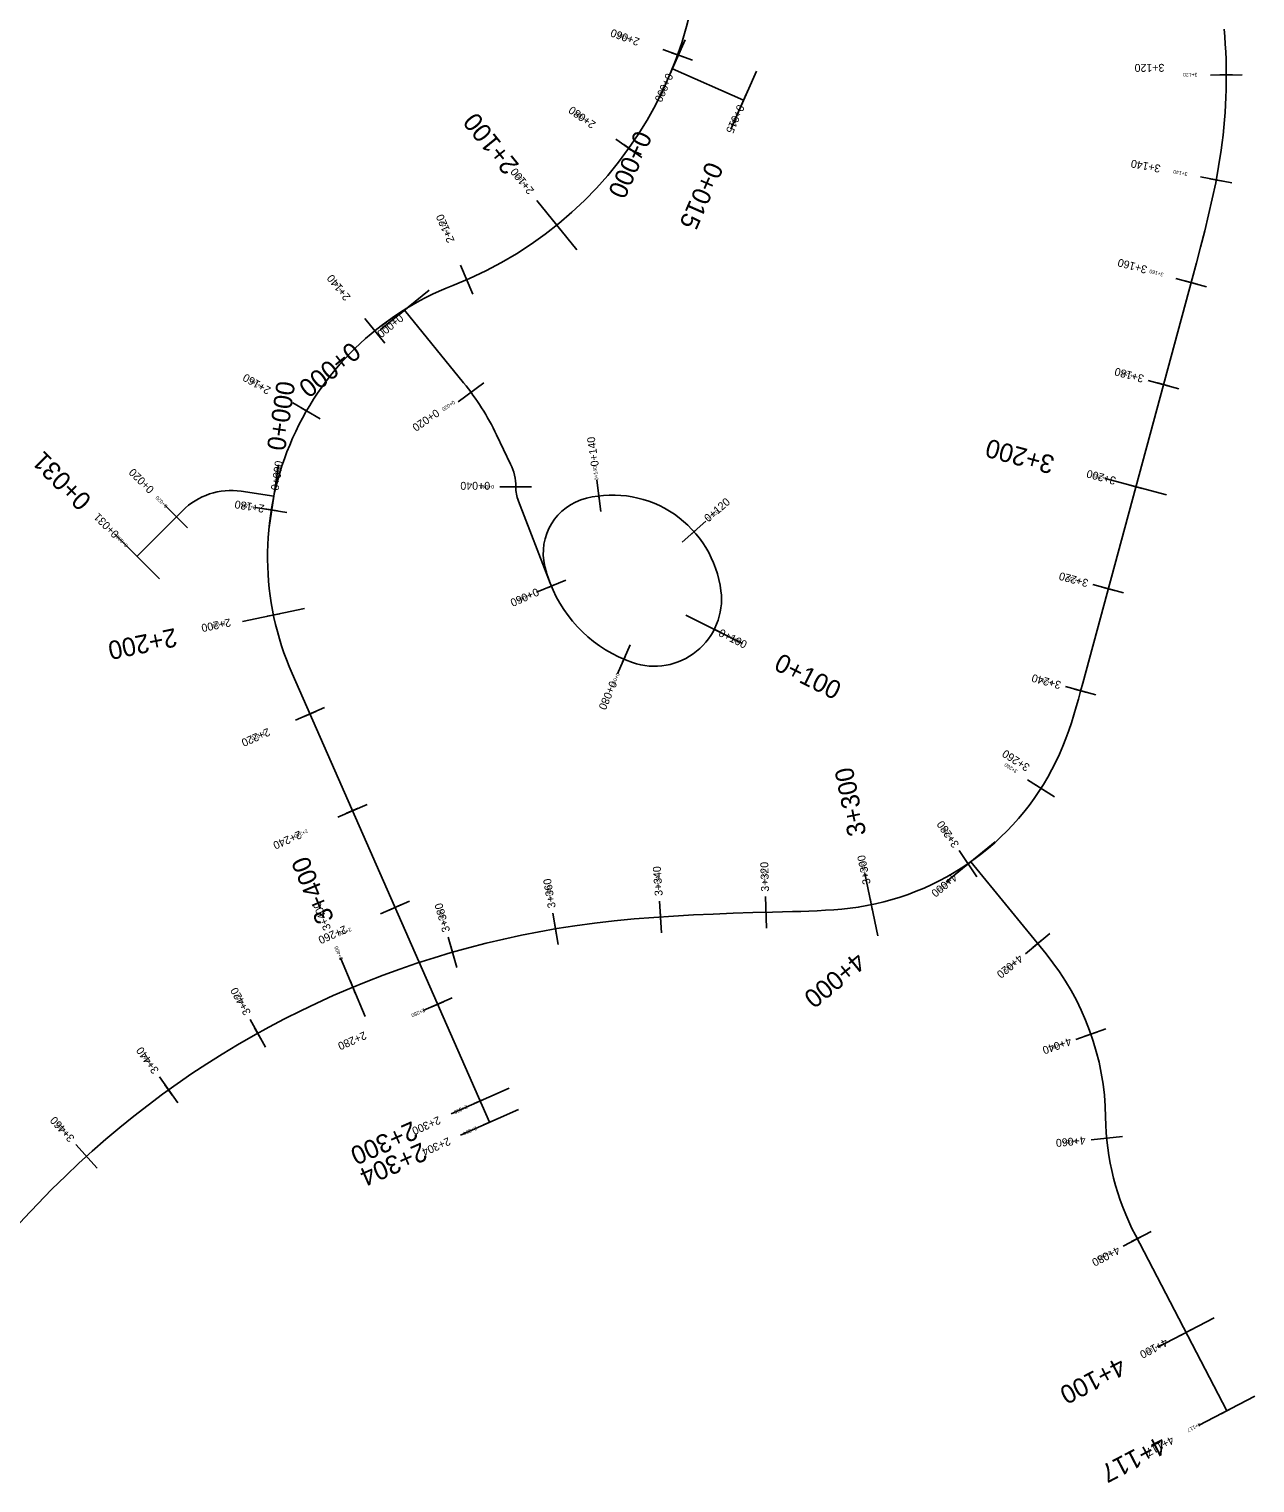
# Model space of a CAD drawing. Extents: x 0 to 511895, y 0 to 6211943.
# Drawn here: x 511516.6 to 511748.6, y 6211454.1 to 6211729.2 of the extents above; entities that cross this region are included whole.
import ezdxf

# ---------------------------------------------------------------- set-up
doc = ezdxf.new("R2010")
doc.units = 0
for name, color, linetype in [('TV_L_---_CL---_C', 7, 'Continuous'), ('TV_L_---_CL---_L', 7, 'Continuous'), ('TV_L_---_CL---_TC', 7, 'Continuous'), ('TV_L_HOR_Statn_T_00200', 7, 'Continuous'), ('TV_L_HOR_Statn_T_00500', 7, 'Continuous'), ('TV_L_HOR_Statn_T_01000', 7, 'Continuous'), ('TV_L_HOR_Statn_Tic_00200', 7, 'Continuous'), ('TV_L_HOR_Statn_Tic_00500', 7, 'Continuous'), ('TV_L_HOR_Statn_Tic_01000', 7, 'Continuous')]:
    doc.layers.add(name, color=color, linetype=linetype)

msp = doc.modelspace()

# ---------------------------------------------------------------- linework, layer by layer
at = {"layer": 'TV_L_---_CL---_C'}
for centre, radius, start, end in [((511570.29, 6211749.09), 73.36, 291.215, 13.0225), ((511643.18, 6211720.15), 100, 352.0321, 5.1862), ((511616.74, 6211629.43), 55, 111.215, 203.7372), ((511560.01, 6211630.79), 50, 25.6143, 39.0403), ((511598.72, 6211642.57), 10, 0.097, 25.6143), ((511554.86, 6211628.89), 13, 81.5953, 135.0684), ((511616.22, 6211642.6), 7.5, 180.097, 201.1169), ((511624.63, 6211630.04), 10.7, 103.7746, 193.7724), ((511627.01, 6211620.33), 20.7, 7.1648, 103.7746), ((511639.2, 6211633.62), 25.7, 193.7724, 200.2452), ((511639.2, 6211633.62), 25.7, 201.1169, 250.9171), ((511634.95, 6211621.33), 12.7, 250.9171, 7.1648), ((511666, 6211612.51), 50, 278.6766, 337.7081), ((511645.09, 6211386.34), 175, 98.2732, 133.988), ((511670.35, 6211522.56), 50, 0.8553, 39.2603), ((511770.34, 6211524.05), 50, 180.8553, 207.4882)]:
    msp.add_arc(centre, radius, start, end, dxfattribs=at)
at = {"layer": 'TV_L_---_CL---_L'}
for p, q in [((511638.35, 6211721.69), (511651.84, 6211715.76)), ((511736.7, 6211681.92), (511716.03, 6211605.46)), ((511587.69, 6211676.04), (511598.84, 6211662.28)), ((511605.09, 6211652.41), (511607.74, 6211646.89)), ((511562.94, 6211640.84), (511556.76, 6211641.75)), ((511609.22, 6211639.9), (511615.23, 6211624.36)), ((511545.66, 6211638.07), (511537.04, 6211629.43)), ((511566.39, 6211607.29), (511603.74, 6211522.36)), ((511694.81, 6211571.64), (511709.07, 6211554.2)), ((511725.99, 6211500.98), (511743.27, 6211467.75))]:
    msp.add_line(p, q, dxfattribs=at)
at = {"layer": 'TV_L_---_CL---_TC'}
for points in [[(511742.21, 6211706.29), (511741.73, 6211703.2), (511741.17, 6211700.13), (511740.53, 6211697.07), (511739.84, 6211694.02), (511739.1, 6211690.99), (511738.32, 6211687.96), (511737.52, 6211684.94), (511736.7, 6211681.92)], [(511716.03, 6211605.46), (511715.62, 6211603.95), (511715.2, 6211602.44), (511714.78, 6211600.94), (511714.33, 6211599.44), (511713.86, 6211597.95), (511713.37, 6211596.47), (511712.84, 6211595), (511712.27, 6211593.54)], [(511673.55, 6211563.08), (511672, 6211562.87), (511670.45, 6211562.7), (511668.89, 6211562.57), (511667.33, 6211562.46), (511665.77, 6211562.38), (511664.21, 6211562.32), (511662.65, 6211562.27), (511661.08, 6211562.23)], [(511661.08, 6211562.23), (511657.33, 6211562.13), (511653.58, 6211562.02), (511649.83, 6211561.9), (511646.08, 6211561.76), (511642.33, 6211561.58), (511638.58, 6211561.37), (511634.84, 6211561.12), (511631.1, 6211560.82), (511627.36, 6211560.45), (511623.63, 6211560.02), (511619.91, 6211559.52)], [(511523.56, 6211512.25), (511520.88, 6211509.62), (511518.26, 6211506.93), (511515.69, 6211504.2), (511513.16, 6211501.43), (511510.66, 6211498.62), (511508.2, 6211495.79), (511505.77, 6211492.93), (511503.36, 6211490.05), (511500.97, 6211487.16), (511498.59, 6211484.26), (511496.21, 6211481.35)]]:
    msp.add_lwpolyline(points, dxfattribs=at)
at = {"layer": 'TV_L_HOR_Statn_Tic_00200'}
for points in [[(511638.83, 6211722.79), (511637.86, 6211720.59)], [(511640.47, 6211723.91), (511638.21, 6211724.72)], [(511744.38, 6211720.52), (511741.98, 6211720.51)], [(511652.32, 6211716.86), (511651.35, 6211714.66)], [(511652.32, 6211716.86), (511651.35, 6211714.66)], [(511652.08, 6211716.31), (511651.6, 6211715.21)], [(511631.1, 6211705.94), (511629.14, 6211707.33)], [(511742.45, 6211700.41), (511740.09, 6211700.87)], [(511617.24, 6211691.16), (511615.73, 6211693.03)], [(511599.91, 6211680.66), (511598.95, 6211682.87)], [(511737.67, 6211680.91), (511735.35, 6211681.53)], [(511588.62, 6211676.79), (511586.76, 6211675.28)], [(511582.79, 6211671.16), (511581.27, 6211673.02)], [(511732.45, 6211661.6), (511730.13, 6211662.23)], [(511600.73, 6211660.83), (511599.76, 6211660.12)], [(511570.17, 6211656.36), (511568.09, 6211657.56)], [(511727.23, 6211642.29), (511724.91, 6211642.92)], [(511562.76, 6211639.65), (511563.11, 6211642.02)], [(511609.32, 6211642.58), (511608.12, 6211642.58)], [(511624.53, 6211640.28), (511624.38, 6211641.47)], [(511545.36, 6211636.07), (511543.66, 6211637.77)], [(511563.63, 6211638.03), (511561.26, 6211638.41)], [(511642.01, 6211633.71), (511642.91, 6211634.51)], [(511537.89, 6211628.59), (511536.19, 6211630.28)], [(511537.89, 6211628.59), (511536.19, 6211630.28)], [(511616, 6211624.03), (511614.89, 6211623.57)], [(511722.01, 6211622.99), (511719.69, 6211623.61)], [(511564.05, 6211618.58), (511561.7, 6211618.09)], [(511645.22, 6211616.16), (511647.37, 6211615.08)], [(511629.41, 6211610.51), (511628.94, 6211609.4)], [(511716.79, 6211603.68), (511714.47, 6211604.31)], [(511570.87, 6211600.1), (511568.67, 6211599.13)], [(511709.13, 6211584.91), (511707.1, 6211586.2)], [(511578.92, 6211581.79), (511576.72, 6211580.82)], [(511694.97, 6211570.29), (511693.61, 6211572.27)], [(511695.74, 6211572.4), (511693.88, 6211570.89)], [(511586.97, 6211563.48), (511584.77, 6211562.52)], [(511656.12, 6211560.9), (511656.05, 6211563.3)], [(511676.25, 6211562.34), (511675.76, 6211564.7)], [(511616.44, 6211557.76), (511616.04, 6211560.13)], [(511636.19, 6211560.01), (511636.02, 6211562.41)], [(511597.08, 6211553.38), (511596.41, 6211555.68)], [(511708.4, 6211556.92), (511706.54, 6211555.4)], [(511578.34, 6211546.81), (511577.42, 6211549.03)], [(511595.02, 6211545.17), (511592.82, 6211544.21)], [(511560.48, 6211538.15), (511559.31, 6211540.25)], [(511718.7, 6211539.43), (511716.43, 6211538.64)], [(511543.72, 6211527.51), (511542.32, 6211529.46)], [(511603.07, 6211526.87), (511600.87, 6211525.9)], [(511604.84, 6211522.84), (511602.64, 6211521.87)], [(511604.84, 6211522.84), (511602.64, 6211521.87)], [(511721.76, 6211519.47), (511719.37, 6211519.24)], [(511528.28, 6211515.03), (511526.67, 6211516.81)], [(511727.38, 6211500.89), (511725.26, 6211499.78)], [(511736.62, 6211483.15), (511734.49, 6211482.04)], [(511744.34, 6211468.31), (511742.21, 6211467.2)], [(511744.34, 6211468.31), (511742.21, 6211467.2)]]:
    msp.add_lwpolyline(points, dxfattribs=at)
at = {"layer": 'TV_L_HOR_Statn_Tic_00500'}
for points in [[(511638.83, 6211722.79), (511637.86, 6211720.59)], [(511640.47, 6211723.91), (511638.21, 6211724.72)], [(511744.38, 6211720.52), (511741.98, 6211720.51)], [(511652.32, 6211716.86), (511651.35, 6211714.66)], [(511652.32, 6211716.86), (511651.35, 6211714.66)], [(511652.08, 6211716.31), (511651.6, 6211715.21)], [(511631.1, 6211705.94), (511629.14, 6211707.33)], [(511742.45, 6211700.41), (511740.09, 6211700.87)], [(511617.24, 6211691.16), (511615.73, 6211693.03)], [(511599.91, 6211680.66), (511598.95, 6211682.87)], [(511737.67, 6211680.91), (511735.35, 6211681.53)], [(511588.62, 6211676.79), (511586.76, 6211675.28)], [(511582.79, 6211671.16), (511581.27, 6211673.02)], [(511732.45, 6211661.6), (511730.13, 6211662.23)], [(511600.73, 6211660.83), (511599.76, 6211660.12)], [(511570.17, 6211656.36), (511568.09, 6211657.56)], [(511727.23, 6211642.29), (511724.91, 6211642.92)], [(511562.76, 6211639.65), (511563.11, 6211642.02)], [(511609.32, 6211642.58), (511608.12, 6211642.58)], [(511624.53, 6211640.28), (511624.38, 6211641.47)], [(511545.36, 6211636.07), (511543.66, 6211637.77)], [(511563.63, 6211638.03), (511561.26, 6211638.41)], [(511642.01, 6211633.71), (511642.91, 6211634.51)], [(511537.89, 6211628.59), (511536.19, 6211630.28)], [(511537.89, 6211628.59), (511536.19, 6211630.28)], [(511616, 6211624.03), (511614.89, 6211623.57)], [(511722.01, 6211622.99), (511719.69, 6211623.61)], [(511564.05, 6211618.58), (511561.7, 6211618.09)], [(511645.22, 6211616.16), (511647.37, 6211615.08)], [(511629.41, 6211610.51), (511628.94, 6211609.4)], [(511716.79, 6211603.68), (511714.47, 6211604.31)], [(511570.87, 6211600.1), (511568.67, 6211599.13)], [(511709.13, 6211584.91), (511707.1, 6211586.2)], [(511578.92, 6211581.79), (511576.72, 6211580.82)], [(511694.97, 6211570.29), (511693.61, 6211572.27)], [(511695.74, 6211572.4), (511693.88, 6211570.89)], [(511586.97, 6211563.48), (511584.77, 6211562.52)], [(511656.12, 6211560.9), (511656.05, 6211563.3)], [(511676.25, 6211562.34), (511675.76, 6211564.7)], [(511616.44, 6211557.76), (511616.04, 6211560.13)], [(511636.19, 6211560.01), (511636.02, 6211562.41)], [(511597.08, 6211553.38), (511596.41, 6211555.68)], [(511708.4, 6211556.92), (511706.54, 6211555.4)], [(511578.34, 6211546.81), (511577.42, 6211549.03)], [(511595.02, 6211545.17), (511592.82, 6211544.21)], [(511560.48, 6211538.15), (511559.31, 6211540.25)], [(511718.7, 6211539.43), (511716.43, 6211538.64)], [(511543.72, 6211527.51), (511542.32, 6211529.46)], [(511603.07, 6211526.87), (511600.87, 6211525.9)], [(511604.84, 6211522.84), (511602.64, 6211521.87)], [(511604.84, 6211522.84), (511602.64, 6211521.87)], [(511721.76, 6211519.47), (511719.37, 6211519.24)], [(511528.28, 6211515.03), (511526.67, 6211516.81)], [(511727.38, 6211500.89), (511725.26, 6211499.78)], [(511736.62, 6211483.15), (511734.49, 6211482.04)], [(511744.34, 6211468.31), (511742.21, 6211467.2)], [(511744.34, 6211468.31), (511742.21, 6211467.2)]]:
    msp.add_lwpolyline(points, dxfattribs=at)
at = {"layer": 'TV_L_HOR_Statn_Tic_01000'}
for points in [[(511640.76, 6211727.18), (511635.93, 6211716.2)], [(511642.17, 6211723.3), (511636.52, 6211725.33)], [(511654.25, 6211721.25), (511649.42, 6211710.27)], [(511746.18, 6211720.53), (511740.18, 6211720.5)], [(511653.05, 6211718.5), (511650.63, 6211713.01)], [(511632.57, 6211704.9), (511627.68, 6211708.37)], [(511744.21, 6211700.07), (511738.32, 6211701.21)], [(511620.26, 6211687.44), (511612.7, 6211696.76)], [(511600.62, 6211679.01), (511598.24, 6211684.52)], [(511739.41, 6211680.44), (511733.62, 6211682)], [(511592.35, 6211679.82), (511583.03, 6211672.26)], [(511583.92, 6211669.76), (511580.14, 6211674.42)], [(511602.66, 6211662.25), (511597.83, 6211658.69)], [(511734.19, 6211661.13), (511728.39, 6211662.69)], [(511571.72, 6211655.45), (511566.53, 6211658.46)], [(511562.06, 6211634.9), (511563.81, 6211646.77)], [(511624.83, 6211637.9), (511624.08, 6211643.85)], [(511731.86, 6211641.04), (511720.28, 6211644.17)], [(511611.72, 6211642.59), (511605.72, 6211642.57)], [(511546.63, 6211634.8), (511542.39, 6211639.04)], [(511565.41, 6211637.74), (511559.49, 6211638.7)], [(511640.22, 6211632.12), (511644.7, 6211636.11)], [(511541.29, 6211625.2), (511532.8, 6211633.67)], [(511541.29, 6211625.2), (511532.8, 6211633.67)], [(511618.22, 6211624.95), (511612.67, 6211622.66)], [(511723.75, 6211622.52), (511717.95, 6211624.08)], [(511568.75, 6211619.55), (511556.99, 6211617.13)], [(511640.93, 6211618.32), (511651.65, 6211612.92)], [(511630.34, 6211612.71), (511628, 6211607.19)], [(511718.52, 6211603.2), (511712.73, 6211604.78)], [(511572.51, 6211600.82), (511567.02, 6211598.41)], [(511710.64, 6211583.94), (511705.59, 6211587.17)], [(511580.57, 6211582.51), (511575.07, 6211580.1)], [(511699.46, 6211575.44), (511690.17, 6211567.85)], [(511695.99, 6211568.81), (511692.6, 6211573.76)], [(511677.21, 6211557.64), (511674.8, 6211569.4)], [(511588.62, 6211564.21), (511583.12, 6211561.79)], [(511636.31, 6211558.22), (511635.9, 6211564.2)], [(511656.17, 6211559.1), (511656, 6211565.1)], [(511616.74, 6211555.99), (511615.75, 6211561.91)], [(511597.57, 6211551.65), (511595.92, 6211557.41)], [(511709.79, 6211558.06), (511705.15, 6211554.26)], [(511580.19, 6211542.38), (511575.58, 6211553.46)], [(511596.67, 6211545.9), (511591.18, 6211543.48)], [(511561.35, 6211536.58), (511558.43, 6211541.82)], [(511720.4, 6211540.02), (511714.73, 6211538.05)], [(511544.77, 6211526.05), (511541.27, 6211530.93)], [(511607.46, 6211528.8), (511596.48, 6211523.97)], [(511609.23, 6211524.77), (511598.25, 6211519.94)], [(511609.23, 6211524.77), (511598.25, 6211519.94)], [(511723.55, 6211519.64), (511717.58, 6211519.07)], [(511529.49, 6211513.7), (511525.46, 6211518.14)], [(511728.98, 6211501.72), (511723.66, 6211498.95)], [(511740.87, 6211485.37), (511730.23, 6211479.83)], [(511748.6, 6211470.52), (511737.95, 6211464.98)], [(511748.6, 6211470.52), (511737.95, 6211464.98)]]:
    msp.add_lwpolyline(points, dxfattribs=at)

# ---------------------------------------------------------------- texts
at = {"layer": 'TV_L_HOR_Statn_T_00200'}
for s, rotation, p in [('2+060', 160.2647, (511630.71, 6211727.51)), ('3+120', 180.2087, (511737.71, 6211720.91)), ('0+000', 246.2556, (511636.96, 6211719.41)), ('2+080', 144.6443, (511622.5, 6211712.02)), ('0+015', 246.2556, (511650.45, 6211713.48)), ('0+015', 246.2556, (511650.45, 6211713.48)), ('2+100', 129.0238, (511610.99, 6211699.64)), ('3+140', 169.1256, (511735.89, 6211702.06)), ('2+120', 113.4034, (511596.19, 6211690.41)), ('2+140', 129.1308, (511576.27, 6211679.49)), ('3+160', 164.8701, (511731.36, 6211683.03)), ('0+000', 219.0403, (511585.41, 6211674.64)), ('2+160', 149.9657, (511560.97, 6211661.7)), ('3+180', 164.8701, (511726.13, 6211663.72)), ('0+020', 214.5261, (511596.92, 6211658.97)), ('0+000', 81.5953, (511563.67, 6211643.41)), ('0+140', 98.1147, (511624.37, 6211643.87)), ('0+040', 180, (511604.62, 6211642.92)), ('3+200', 164.8701, (511720.83, 6211644.4)), ('0+020', 135.0684, (511542.88, 6211639.04)), ('2+180', 170.8005, (511559.64, 6211638.99)), ('0+120', 40.867, (511645.14, 6211636.04)), ('0+031', 135.0684, (511535.37, 6211631.6)), ('0+031', 135.0684, (511535.37, 6211631.6)), ('3+220', 164.8701, (511715.61, 6211625.03)), ('0+060', 203.7372, (511611.44, 6211622.5)), ('2+200', 191.6353, (511553.7, 6211617.14)), ('0+100', 333.2883, (511648.51, 6211614.12)), ('0+080', 246.6106, (511627.78, 6211607.49)), ('3+240', 164.7646, (511710.45, 6211605.74)), ('2+220', 203.7372, (511561.09, 6211596.32)), ('3+260', 147.3754, (511703.75, 6211588.92)), ('2+240', 203.7372, (511569.2, 6211577.84)), ('3+280', 124.4571, (511691.5, 6211575.98)), ('3+300', 101.5388, (511675.2, 6211568.93)), ('3+340', 93.9933, (511636.03, 6211566.74)), ('3+320', 91.6138, (511656.2, 6211567.54)), ('3+360', 99.49, (511615.64, 6211564.46)), ('4+000', 219.2603, (511690.62, 6211568.26)), ('3+380', 106.0381, (511595.51, 6211559.93)), ('2+260', 203.7372, (511577.43, 6211559.22)), ('3+400', 112.5862, (511576.04, 6211553.25)), ('4+020', 219.2603, (511703.01, 6211552.91)), ('3+420', 119.1343, (511557.56, 6211544.27)), ('2+280', 203.7372, (511591.35, 6211543.94)), ('4+040', 199.2356, (511712.25, 6211537.57)), ('3+440', 125.6824, (511540.05, 6211533.22)), ('2+300', 203.7372, (511599.4, 6211525.64)), ('3+460', 132.2304, (511524, 6211520.31)), ('2+304', 203.7372, (511601.17, 6211521.61)), ('2+304', 203.7372, (511601.17, 6211521.61)), ('4+060', 185.3933, (511714.99, 6211519.16)), ('4+080', 207.4882, (511721.23, 6211498.17)), ('4+100', 207.4882, (511730.46, 6211480.45)), ('4+117', 207.4882, (511738.13, 6211465.58))]:
    msp.add_text(s, height=0.7, rotation=rotation, dxfattribs=at).set_placement(p)
at = {"layer": 'TV_L_HOR_Statn_T_00500'}
for s, rotation, p in [('2+060', 160.2647, (511632.29, 6211727.37)), ('3+120', 180.2087, (511731.46, 6211722.61)), ('0+000', 246.2556, (511637.21, 6211720.98)), ('2+080', 144.6443, (511623.99, 6211711.45)), ('0+015', 246.2556, (511650.71, 6211715.05)), ('0+015', 246.2556, (511650.71, 6211715.05)), ('3+140', 169.1256, (511730.83, 6211703.46)), ('2+100', 129.0238, (511612.28, 6211698.69)), ('2+120', 113.4034, (511597.17, 6211689.16)), ('3+160', 164.8701, (511728.32, 6211684.33)), ('2+140', 129.1308, (511577.56, 6211678.55)), ('0+000', 219.0403, (511586.69, 6211675.37)), ('3+180', 164.8701, (511727.72, 6211663.7)), ('2+160', 149.9657, (511562.51, 6211661.27)), ('0+020', 214.5261, (511593.62, 6211657.39)), ('0+140', 98.1147, (511624.45, 6211646.56)), ('0+020', 135.0684, (511540.4, 6211642.23)), ('0+000', 81.5953, (511563.84, 6211641.82)), ('3+200', 164.8701, (511722.42, 6211644.38)), ('0+040', 180, (511603.87, 6211643.53)), ('2+180', 170.8005, (511561.23, 6211639.14)), ('0+120', 40.867, (511645.17, 6211635.82)), ('0+031', 135.0684, (511533.76, 6211633.78)), ('3+220', 164.8701, (511717.21, 6211625.01)), ('0+060', 203.7372, (511612.69, 6211623.49)), ('2+200', 191.6353, (511554.63, 6211617.69)), ('0+100', 333.2883, (511646.95, 6211614.45)), ('3+240', 164.7646, (511712.04, 6211605.72)), ('0+080', 246.6106, (511626.58, 6211606)), ('2+220', 203.7372, (511561.81, 6211597)), ('3+260', 147.3754, (511706.14, 6211589.91)), ('3+280', 124.4571, (511692.7, 6211574.94)), ('2+240', 203.7372, (511567.79, 6211577.57)), ('3+320', 91.6138, (511656.65, 6211566.01)), ('3+300', 101.5388, (511675.9, 6211567.5)), ('3+360', 99.49, (511616.29, 6211563)), ('3+340', 93.9933, (511636.53, 6211565.23)), ('4+000', 219.2603, (511691.56, 6211569.55)), ('3+400', 112.5862, (511573.8, 6211559.03)), ('3+380', 106.0381, (511596.32, 6211558.56)), ('2+260', 203.7372, (511576.35, 6211559.66)), ('4+020', 219.2603, (511703.95, 6211554.2)), ('3+420', 119.1343, (511558.66, 6211543.12)), ('2+280', 203.7372, (511580.06, 6211539.59)), ('4+040', 199.2356, (511713.57, 6211538.45)), ('3+440', 125.6824, (511541.27, 6211532.21)), ('3+460', 132.2304, (511525.33, 6211519.44)), ('2+300', 203.7372, (511594.08, 6211523.55)), ('2+304', 203.7372, (511595.96, 6211519.56)), ('4+060', 185.3933, (511716.48, 6211519.7)), ('4+080', 207.4882, (511722.58, 6211498.95)), ('4+100', 207.4882, (511731.64, 6211481.52)), ('4+117', 207.4882, (511732.81, 6211463.04))]:
    msp.add_text(s, height=1.5, rotation=rotation, dxfattribs=at).set_placement(p)
at = {"layer": 'TV_L_HOR_Statn_T_01000'}
for s, rotation, p in [('2+100', 129.0238, (511609.5, 6211703.49)), ('0+000', 246.2556, (511631.41, 6211710.27)), ('0+015', 246.2556, (511644.91, 6211704.35)), ('0+015', 246.2556, (511644.91, 6211704.35)), ('0+000', 219.0403, (511577.53, 6211670.21)), ('0+000', 81.5953, (511565.07, 6211649.26)), ('3+200', 164.8701, (511710.92, 6211648.31)), ('0+031', 135.0684, (511528.66, 6211640.27)), ('0+031', 135.0684, (511528.66, 6211640.27)), ('2+200', 191.6353, (511544.2, 6211615.89)), ('0+100', 333.2883, (511657.35, 6211608.1)), ('3+300', 101.5388, (511675.07, 6211576.86)), ('3+400', 112.5862, (511574.41, 6211560.83)), ('4+000', 219.2603, (511673.12, 6211554.75)), ('2+300', 203.7372, (511589.14, 6211522.65)), ('2+304', 203.7372, (511590.9, 6211518.62)), ('2+304', 203.7372, (511590.9, 6211518.62)), ('4+100', 207.4882, (511722.99, 6211478.03)), ('4+117', 207.4882, (511730.72, 6211463.19)), ('4+117', 207.4882, (511730.72, 6211463.19))]:
    msp.add_text(s, height=3.5, rotation=rotation, dxfattribs=at).set_placement(p)

doc.saveas('drawing.dxf')
